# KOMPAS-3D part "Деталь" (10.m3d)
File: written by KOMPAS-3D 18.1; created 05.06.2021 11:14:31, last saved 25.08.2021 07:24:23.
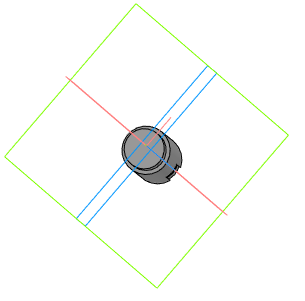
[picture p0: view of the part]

Document properties: Автор: 111; Полное имя файла: C:\Users\admin\Desktop\ffb\10.m3d

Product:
- Part/product: Деталь
    Масса: 0.0680655
    source file: 5.cdw
  - Body: Тело 6
      Масса: 0.00623179
  - Body: Тело 5
      Масса: 0.00617009
  - Body: Тело 4
      Масса: 0.0556636

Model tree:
1. Эскиз:6
2. Элемент выдавливания:6
     Расстояние 1 = 64
3. Эскиз:7
4. Эскиз:9  (with: Элемент выдавливания:6)
5. Элемент выдавливания:7
     Расстояние 1 = 10
6. Эскиз:10
7. Элемент выдавливания:8
     Расстояние 1 = -10.1
8. Эскиз:11  (with: Элемент выдавливания:6)
9. Элемент выдавливания:9
     Расстояние 2 = 21
10. Эскиз:12
11. Элемент выдавливания:10
     Расстояние 2 = 21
